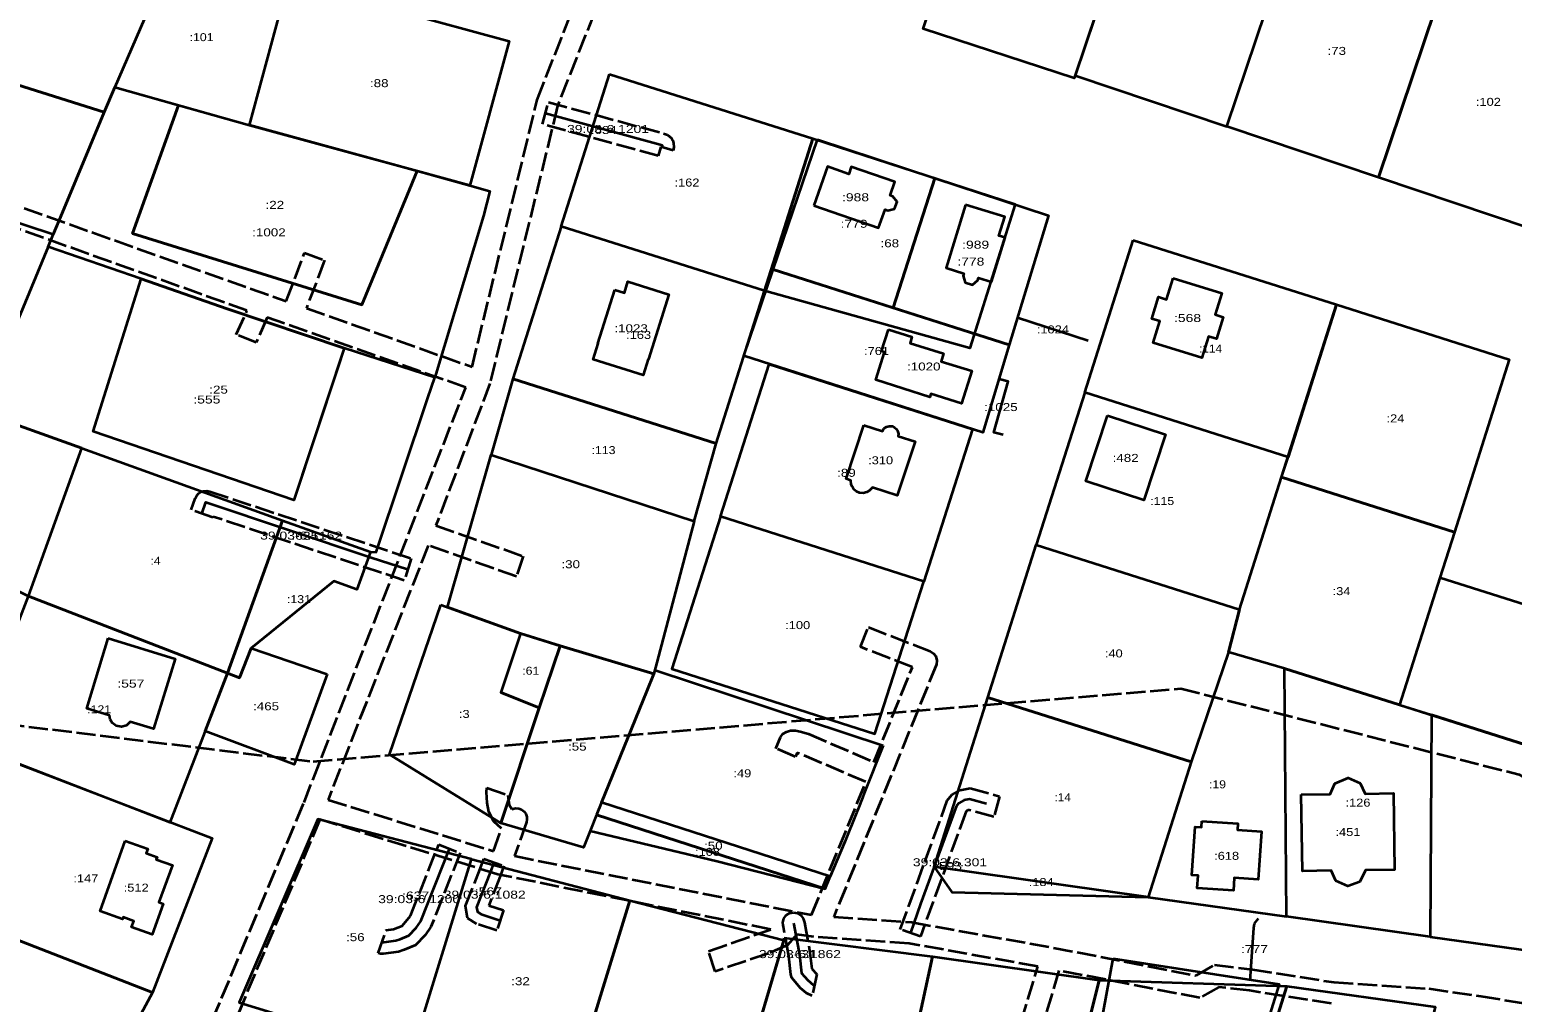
# Model space of a CAD drawing. Extents: x 1185507 to 1197690, y 352608 to 375774.
# Drawn here: x 1190399.7 to 1190677.6, y 364414.2 to 364596.7 of the extents above; entities that cross this region are included whole.
import ezdxf
from ezdxf.enums import TextEntityAlignment as Align

# ---------------------------------------------------------------- set-up
doc = ezdxf.new("R2010")
doc.units = 0
doc.header["$LTSCALE"] = 0.6
doc.linetypes.add('LONG_DASHED', pattern=[7.5, 6, -1.5])
for name, color, linetype, lineweight in [('2', 7, 'Continuous', 35), ('7', 7, 'LONG_DASHED', 35), ('8', 7, 'Continuous', 35)]:
    doc.layers.add(name, color=color, linetype=linetype, lineweight=lineweight)

msp = doc.modelspace()

# ---------------------------------------------------------------- linework, layer by layer
at = {"layer": '2'}
for points in [[(1190580.02, 364635.14), (1190608.39, 364625.95), (1190595.5, 364587.56), (1190567.19, 364596.87)], [(1190636.88, 364616.44), (1190608.44, 364626), (1190595.7, 364588.08), (1190624.14, 364578.52)], [(1190390.15, 364622), (1190419.82, 364614.11), (1190426.83, 364611.77), (1190415.6, 364585.92), (1190413.64, 364581.23), (1190379.72, 364591.89), (1190388.94, 364618.53)], [(1190636.88, 364616.44), (1190665.31, 364606.88), (1190652.56, 364568.96), (1190624.14, 364578.52)], [(1190448.18, 364605.82), (1190426.83, 364611.77), (1190415.6, 364585.92), (1190440.87, 364578.79)], [(1190448.18, 364605.82), (1190489.54, 364594.5), (1190482.19, 364567.48), (1190440.87, 364578.79)], [(1190665.31, 364606.88), (1190693.75, 364597.33), (1190681, 364559.41), (1190652.56, 364568.96)], [(1190379.72, 364591.89), (1190413.64, 364581.23), (1190405.75, 364562.26), (1190404.09, 364558.27), (1190393.92, 364561.55), (1190395.35, 364565.66), (1190397.61, 364572.21), (1190393.97, 364573.3), (1190390.13, 364574.45), (1190375.41, 364578.85), (1190375.82, 364580.49), (1190375.86, 364580.73)], [(1190508.38, 364588.35), (1190546.5, 364576.26), (1190537.43, 364547.66), (1190499.3, 364559.76)], [(1190415.6, 364585.92), (1190427.54, 364582.55), (1190418.97, 364558.44), (1190461.97, 364545.09), (1190470.43, 364565.64), (1190472.3, 364570.19), (1190482.19, 364567.48), (1190485.93, 364566.36), (1190484.73, 364561.73), (1190475.61, 364531.4), (1190458.61, 364536.92), (1190436.72, 364544.33), (1190420.58, 364549.92), (1190403.12, 364555.96), (1190404.09, 364558.27), (1190405.75, 364562.26), (1190413.65, 364581.23)], [(1190427.54, 364582.55), (1190440.87, 364578.79), (1190472.3, 364570.19), (1190470.43, 364565.64), (1190461.97, 364545.09), (1190418.97, 364558.44)], [(1190546.5, 364576.26), (1190584.43, 364563.93), (1190575.92, 364536.96), (1190537.43, 364547.66)], [(1190547.4, 364576.06), (1190569.38, 364568.83), (1190561.59, 364544.48), (1190539.09, 364551.67)], [(1190569.38, 364568.83), (1190590.66, 364561.84), (1190583.33, 364537.53), (1190561.59, 364544.48)], [(1190537.43, 364547.66), (1190499.3, 364559.76), (1190490.23, 364531.17), (1190528.35, 364519.07)], [(1190606.54, 364557.2), (1190644.66, 364545.1), (1190635.6, 364516.5), (1190597.47, 364528.6)], [(1190403.12, 364555.96), (1190397.62, 364542.61), (1190395.42, 364537.28), (1190390.17, 364525.06), (1190409.42, 364518.15), (1190447.07, 364504.63), (1190463.54, 364498.72), (1190464.61, 364498.63), (1190474.33, 364527.61), (1190475.61, 364531.4), (1190458.61, 364536.92), (1190457.36, 364533.13), (1190449.18, 364508.39), (1190411.55, 364521.27), (1190420.58, 364549.92)], [(1190539.09, 364551.67), (1190583.33, 364537.53), (1190578.4, 364521.14), (1190533.56, 364535.47)], [(1190420.58, 364549.92), (1190436.72, 364544.33), (1190458.61, 364536.92), (1190449.18, 364508.39), (1190411.55, 364521.27)], [(1190644.67, 364545.1), (1190677.08, 364534.82), (1190666.8, 364502.41), (1190634.39, 364512.7)], [(1190538.33, 364533.93), (1190576.42, 364521.74), (1190567.28, 364493.17), (1190529.18, 364505.36)], [(1190486.16, 364516.93), (1190524.23, 364504.45), (1190528.35, 364519.07), (1190490.23, 364531.17)], [(1190635.6, 364516.5), (1190597.47, 364528.6), (1190588.4, 364500.01), (1190626.52, 364487.91), (1190634.39, 364512.7)], [(1190409.42, 364518.15), (1190390.17, 364525.06), (1190382.4, 364507.25), (1190391.55, 364494.27), (1190399.45, 364490.39)], [(1190409.42, 364518.15), (1190447.07, 364504.63), (1190436.76, 364475.93), (1190399.45, 364490.39)], [(1190477.98, 364488.36), (1190486.16, 364516.93), (1190524.23, 364504.45), (1190516.66, 364475.86), (1190499.15, 364481.1), (1190491.7, 364483.43)], [(1190624.44, 364479.92), (1190626.52, 364487.91), (1190634.39, 364512.7), (1190666.8, 364502.41), (1190664.07, 364493.84), (1190656.51, 364470), (1190634.95, 364476.85)], [(1190463.54, 364498.72), (1190461, 364491.66), (1190456.68, 364493.22), (1190441.17, 364480.66), (1190439, 364475.06), (1190436.76, 364475.93), (1190447.07, 364504.63)], [(1190567.28, 364493.17), (1190529.18, 364505.36), (1190520.04, 364476.78), (1190558.13, 364464.59)], [(1190588.4, 364500.01), (1190626.52, 364487.91), (1190624.44, 364479.92), (1190617.45, 364459.32), (1190579.32, 364471.42)], [(1190682.39, 364492.06), (1190681.23, 364488.39), (1190664.07, 364493.84), (1190656.51, 364470), (1190698.44, 364456.69), (1190707.18, 364484.19)], [(1190436.76, 364475.93), (1190425.92, 364447.96), (1190388.63, 364462.41), (1190399.45, 364490.39)], [(1190476.78, 364488.79), (1190491.7, 364483.43), (1190487.98, 364472.31), (1190495.19, 364469.46), (1190488.02, 364447.83), (1190467.1, 364460.71)], [(1190488.09, 364472.34), (1190491.77, 364483.38), (1190499.15, 364481.1), (1190495.19, 364469.46)], [(1190455.42, 364475.8), (1190449.28, 364458.83), (1190432.55, 364465.07), (1190436.76, 364475.93), (1190439, 364475.06), (1190441.17, 364480.66)], [(1190495.19, 364469.46), (1190499.15, 364481.1), (1190516.66, 364475.86), (1190515.38, 364472.61), (1190506.88, 364451.68), (1190505.94, 364449.37), (1190504.73, 364446.38), (1190503.53, 364443.26), (1190488.02, 364447.83)], [(1190624.44, 364479.92), (1190617.45, 364459.32), (1190609.4, 364433.94), (1190635.32, 364430.28), (1190634.95, 364476.85)], [(1190559.69, 364462.39), (1190556.12, 364453.45), (1190555.8, 364452.6), (1190554.99, 364450.48), (1190554.71, 364449.73), (1190552.47, 364444.34), (1190551.1, 364441.07), (1190549.74, 364437.81), (1190506.88, 364451.68), (1190515.38, 364472.61), (1190516.66, 364475.86), (1190516.96, 364476.55)], [(1190634.95, 364476.85), (1190656.51, 364470), (1190662.46, 364468.12), (1190662.24, 364426.49), (1190635.32, 364430.28)], [(1190579.32, 364471.42), (1190617.45, 364459.32), (1190609.4, 364433.94), (1190569.23, 364439.6)], [(1190698.44, 364456.69), (1190662.46, 364468.12), (1190662.24, 364426.49), (1190687.72, 364422.9), (1190698.15, 364455.75)], [(1190397.68, 364458.91), (1190433.86, 364445.01), (1190422.7, 364416.02), (1190386.53, 364430.1)], [(1190506.88, 364451.68), (1190505.94, 364449.37), (1190548.79, 364435.51), (1190549.74, 364437.81)], [(1190505.94, 364449.37), (1190504.73, 364446.38), (1190528.54, 364440.71), (1190548.79, 364435.51)], [(1190482.5, 364441.06), (1190453.71, 364448.57), (1190438.94, 364414.18), (1190471.2, 364404.29)], [(1190482.5, 364441.06), (1190512.2, 364433.34), (1190500.51, 364395.28), (1190471.2, 364404.29)], [(1190609.4, 364433.94), (1190569.23, 364439.6), (1190572.53, 364434.9)], [(1190377.5, 364433.71), (1190386.53, 364430.1), (1190422.7, 364416.02), (1190412.2, 364396.54), (1190398.99, 364372.06), (1190382.22, 364376.24), (1190378.43, 364377.18), (1190370.06, 364414.67), (1190372.09, 364419.87)], [(1190512.2, 364433.34), (1190541.04, 364425.84), (1190529.71, 364387.33), (1190500.51, 364395.28)], [(1190541.14, 364426.28), (1190568.91, 364422.79), (1190560.72, 364385), (1190560.1, 364382.18), (1190529.71, 364387.33), (1190541.04, 364425.84)], [(1190568.91, 364422.79), (1190600.18, 364418.38), (1190590.77, 364380.48), (1190560.72, 364385)], [(1190602.8, 364422.44), (1190633.95, 364417.63), (1190620.97, 364375.98), (1190594.87, 364379.16)], [(1190600.18, 364418.38), (1190635.34, 364417.21), (1190624.43, 364382.3), (1190591.51, 364383.45)], [(1190635.34, 364417.21), (1190663.17, 364413.36), (1190662.28, 364409.63), (1190661.35, 364405.72), (1190654.11, 364375.27), (1190653.46, 364372.51), (1190623.38, 364379.05), (1190624.43, 364382.3), (1190633.8, 364412.26), (1190634.99, 364416.08)]]:
    msp.add_lwpolyline(points, close=True, dxfattribs=at)
at = {"layer": '7'}
for points in [[(1190390.14, 364566.2), (1190447.76, 364545.74), (1190451.22, 364554.84), (1190454.96, 364553.42), (1190451.55, 364544.45), (1190482.61, 364533.41), (1190494.81, 364583.53), (1190504.74, 364608.72), (1190490.08, 364620.47), (1190489.64, 364621.08), (1190489.45, 364621.8), (1190489.55, 364622.55), (1190489.92, 364623.22), (1190498.88, 364634.62), (1190518.92, 364673.75), (1190545.81, 364714.13), (1190550.54, 364722.34), (1190549.28, 364723.55), (1190536.3, 364747.95), (1190523.65, 364763.79), (1190521.95, 364765.46), (1190506.35, 364767.58), (1190505.27, 364771.78)], [(1190508.85, 364608.28), (1190498.64, 364582.41), (1190485.96, 364530.3), (1190475.82, 364503.67), (1190492.18, 364497.92), (1190490.92, 364494.12), (1190474.39, 364499.93), (1190455.6, 364452.22), (1190486.65, 364442.57), (1190488.14, 364446.84), (1190486.68, 364448.15), (1190485.77, 364449.92), (1190485.42, 364451.66), (1190485.29, 364453.65), (1190485.4, 364454.44), (1190489.34, 364453.1), (1190489.59, 364451.24), (1190490.08, 364450.47), (1190490.76, 364450.63), (1190491.39, 364450.58), (1190491.85, 364450.39), (1190492.35, 364450.01), (1190492.67, 364449.55), (1190492.86, 364449.02), (1190492.89, 364448.51), (1190492.79, 364448.02), (1190490.57, 364441.66), (1190546.25, 364430.6), (1190556.45, 364455.57), (1190543.57, 364461.04), (1190543.25, 364460.24), (1190539.59, 364461.85), (1190540.46, 364463.97), (1190540.9, 364464.58), (1190541.53, 364464.98), (1190542.34, 364465.2), (1190543.26, 364465.18), (1190544.11, 364465.01), (1190545.7, 364464.58), (1190557.95, 364459.28), (1190565.16, 364477.09), (1190555.44, 364480.89), (1190556.92, 364484.61), (1190568.51, 364480.07), (1190569.14, 364479.67), (1190569.53, 364479.15), (1190569.77, 364478.34), (1190569.67, 364477.59), (1190550.42, 364430.24), (1190565.04, 364429.22), (1190591.64, 364424.45), (1190618.37, 364419.24), (1190621.81, 364421.21), (1190628.91, 364420.37), (1190644.21, 364417.96), (1190661.99, 364416.78), (1190671.72, 364415.36), (1190683.02, 364413.49)], [(1189191.9, 364549.27), (1189395.22, 364588.56), (1189548.85, 364595.13), (1189680.04, 364579.91), (1189784.57, 364598.37), (1189872.95, 364591.01), (1190232.66, 364472.66), (1190283.77, 364463.98), (1190368.24, 364469.75), (1190452.8, 364459.37), (1190615.51, 364473.08), (1190678.91, 364456.96), (1190881.18, 364333.99), (1190940.56, 364356.34), (1190991.35, 364354.82), (1191177.32, 364502.05)], [(1190481.42, 364529.58), (1190444.22, 364542.68), (1190442.12, 364537.97), (1190438.41, 364539.48), (1190440.41, 364543.98), (1190388.71, 364562.46)], [(1190432.15, 364406.69), (1190451.1, 364451.71), (1190481.42, 364529.58)], [(1190585.51, 364410.41), (1190588.69, 364420.92), (1190564.54, 364425.24), (1190546.69, 364426.49), (1190543.52, 364426.96), (1190541.73, 364424.92), (1190538.19, 364423.38), (1190528.17, 364420.02), (1190526.95, 364423.83), (1190538.6, 364427.88), (1190487.42, 364438.21), (1190454.09, 364448.5), (1190435.81, 364405.08)], [(1190643.74, 364413.98), (1190628.38, 364416.4), (1190622.63, 364417.08), (1190619.08, 364415.02), (1190592.65, 364420.18), (1190589.41, 364409.53)]]:
    msp.add_lwpolyline(points, dxfattribs=at)
for points in [[(1190496.92, 364583.11), (1190518.52, 364577.22), (1190519.23, 364576.94), (1190519.64, 364576.67), (1190519.99, 364576.31), (1190520.24, 364575.87), (1190520.38, 364575.39), (1190520.41, 364574.64), (1190520.3, 364574.02), (1190518.03, 364574.7), (1190517.51, 364573.01), (1190495.79, 364578.96)], [(1190429.93, 364506.58), (1190430.69, 364508.74), (1190430.99, 364509.32), (1190431.34, 364509.68), (1190431.75, 364509.95), (1190432.22, 364510.12), (1190432.85, 364510.17), (1190433.47, 364510.05), (1190471.18, 364497.49), (1190469.88, 364493.37), (1190434.05, 364505.32), (1190434, 364505.17)], [(1190581.52, 364452.83), (1190580.43, 364448.98), (1190575.82, 364450.28), (1190575.56, 364450.23), (1190575.22, 364450.04), (1190566.68, 364426.57), (1190562.9, 364427.89), (1190571.7, 364452.05), (1190572.57, 364453.13), (1190574.14, 364454.03), (1190575.98, 364454.4)], [(1190466.48, 364427.72), (1190467.87, 364427.92), (1190469.52, 364428.56), (1190471.08, 364430.44), (1190476.36, 364443.82), (1190480.37, 364442.25), (1190474.9, 364428.38), (1190473.8, 364426.82), (1190472.02, 364424.96), (1190469.85, 364424.03), (1190468.81, 364423.7), (1190465.96, 364423.31), (1190465.46, 364423.31), (1190465, 364423.42)], [(1190484.8, 364441.14), (1190488.56, 364439.8), (1190487.87, 364437.86), (1190485.73, 364432.39), (1190488.49, 364431.48), (1190487.23, 364427.68), (1190483.42, 364428.94), (1190481.77, 364430.02), (1190481.4, 364432.29), (1190484.13, 364439.26)], [(1190547.27, 364419.49), (1190546.36, 364415.44), (1190545.33, 364415.93), (1190544.19, 364416.89), (1190542.58, 364418.8), (1190542.4, 364419.43), (1190542.02, 364422.85), (1190541, 364428.38), (1190540.92, 364428.7), (1190540.89, 364429.2), (1190541.08, 364429.93), (1190541.52, 364430.53), (1190542.15, 364430.93), (1190542.89, 364431.07), (1190543.62, 364430.93), (1190544.26, 364430.53), (1190544.7, 364429.93), (1190544.92, 364429.21), (1190545.96, 364423.52), (1190546.31, 364420.51)]]:
    msp.add_lwpolyline(points, close=True, dxfattribs=at)
at = {"layer": '8'}
msp.add_line((1190598.12, 364538.28), (1190584.89, 364542.62), dxfattribs=at)
for points in [[(1190496.36, 364581.03), (1190517.86, 364575.17), (1190518.26, 364575.02), (1190518.26, 364574.69)], [(1190582.2, 364520.67), (1190580.41, 364521.12), (1190583.11, 364530.66), (1190581.41, 364531.09)], [(1190431.97, 364505.88), (1190432.72, 364508.03), (1190463.68, 364497.63), (1190470.53, 364495.44)], [(1190579.05, 364451.45), (1190575.9, 364452.34), (1190574.85, 364452.13), (1190573.89, 364451.58), (1190573.46, 364451.05), (1190566.7, 364432.69), (1190564.79, 364427.23)], [(1190465.71, 364425.45), (1190468.34, 364425.81), (1190469.11, 364426.05), (1190470.77, 364426.76), (1190472.13, 364428.19), (1190472.99, 364429.41), (1190478.36, 364443.03)], [(1190486.68, 364440.47), (1190486, 364438.56), (1190483.46, 364432.07), (1190483.6, 364431.21), (1190484.29, 364430.76), (1190487.86, 364429.58)], [(1190628.58, 364418.46), (1190628.53, 364419.04), (1190628.59, 364420.06), (1190629.17, 364428.21), (1190629.3, 364429.01), (1190630.06, 364429.94)], [(1190542.89, 364429.07), (1190542.95, 364428.83), (1190544, 364423.14), (1190544.39, 364419.66), (1190544.94, 364419.05), (1190545.22, 364418.74), (1190545.26, 364418.69), (1190545.56, 364418.35), (1190546.62, 364417.45), (1190546.64, 364417.44)]]:
    msp.add_lwpolyline(points, dxfattribs=at)
for points in [[(1190546.7, 364563.71), (1190558.84, 364559.5), (1190560.04, 364562.94), (1190560.59, 364562.75), (1190561.84, 364563.07), (1190562.3, 364564.39), (1190561.51, 364565.39), (1190561, 364565.57), (1190561.88, 364568.11), (1190553.69, 364570.96), (1190553.22, 364569.6), (1190549.22, 364570.99)], [(1190575.15, 364563.85), (1190571.51, 364551.99), (1190574.82, 364550.97), (1190574.68, 364550.51), (1190575.06, 364549.26), (1190576.43, 364548.84), (1190577.43, 364549.66), (1190577.57, 364550.13), (1190580, 364549.38), (1190582.54, 364557.67), (1190581.38, 364558.03), (1190582.48, 364561.6)], [(1190509.4, 364547.87), (1190511.16, 364547.31), (1190511.84, 364549.46), (1190519.53, 364547.01), (1190515.71, 364534.85), (1190515.63, 364534.88), (1190514.67, 364531.87), (1190505.32, 364534.81), (1190506.26, 364537.8), (1190506.2, 364537.82)], [(1190614.08, 364550.08), (1190623.21, 364547.23), (1190621.96, 364543.23), (1190623.45, 364542.77), (1190622.2, 364538.66), (1190620.67, 364539.11), (1190619.42, 364535.1), (1190610.28, 364537.96), (1190611.54, 364541.98), (1190610.05, 364542.43), (1190611.31, 364546.56), (1190612.83, 364546.09)], [(1190560.69, 364540.44), (1190565.07, 364539.06), (1190564.72, 364537.9), (1190571, 364535.91), (1190570.54, 364534.46), (1190576.3, 364532.65), (1190574.37, 364526.55), (1190568.6, 364528.34), (1190568.42, 364527.77), (1190558.29, 364530.99), (1190559.93, 364536.18), (1190559.36, 364536.36)], [(1190601.75, 364524.3), (1190612.6, 364520.74), (1190608.55, 364508.39), (1190597.69, 364511.95)], [(1190556.05, 364522.5), (1190559.53, 364521.39), (1190559.82, 364521.83), (1190560.3, 364522.19), (1190560.84, 364522.33), (1190561.38, 364522.3), (1190561.84, 364522.08), (1190562.14, 364521.82), (1190562.4, 364521.4), (1190562.54, 364520.86), (1190562.51, 364520.45), (1190565.66, 364519.45), (1190562.32, 364509.3), (1190557.66, 364510.81), (1190557.13, 364510.22), (1190556.6, 364509.9), (1190555.96, 364509.75), (1190555.23, 364509.8), (1190554.66, 364510.05), (1190554.2, 364510.44), (1190553.86, 364510.96), (1190553.7, 364511.38), (1190553.65, 364512.11), (1190552.75, 364512.41)], [(1190414.38, 364482.51), (1190426.92, 364478.64), (1190422.89, 364465.49), (1190418.51, 364466.82), (1190417.8, 364466.15), (1190416.86, 364465.88), (1190415.9, 364466.05), (1190415.12, 364466.63), (1190414.75, 364467.27), (1190414.63, 364468.03), (1190410.35, 364469.35)], [(1190638.07, 364453.19), (1190643.5, 364453.25), (1190644.35, 364455.23), (1190646.85, 364456.31), (1190649.1, 364455.34), (1190650.03, 364453.32), (1190655.38, 364453.43), (1190655.58, 364439.07), (1190650.12, 364439.01), (1190649.05, 364436.84), (1190646.78, 364436.02), (1190644.56, 364437), (1190643.67, 364438.96), (1190638.3, 364438.83)], [(1190619.44, 364448.21), (1190626.2, 364447.75), (1190626.12, 364446.57), (1190630.61, 364446.27), (1190629.99, 364437.27), (1190625.5, 364437.57), (1190625.34, 364435.17), (1190618.57, 364435.63), (1190618.73, 364437.99), (1190617.55, 364438.07), (1190618.17, 364447.12), (1190619.36, 364447.04)], [(1190417.58, 364444.52), (1190421.81, 364442.98), (1190421.52, 364442.18), (1190423.55, 364441.45), (1190423.39, 364441), (1190426.42, 364439.91), (1190423.91, 364432.97), (1190424.69, 364432.69), (1190422.61, 364426.92), (1190418.75, 364428.31), (1190419.18, 364429.45), (1190417.21, 364430.18), (1190417.08, 364429.82), (1190412.85, 364431.34)]]:
    msp.add_lwpolyline(points, close=True, dxfattribs=at)

# ---------------------------------------------------------------- texts
at = {"layer": '2'}
for s, width, p in [(':101', 1.15, (1190431.8895, 364594.53)), (':73', 1.25, (1190644.7245, 364591.95)), (':88', 1.25, (1190465.2045, 364585.9)), (':102', 1.2, (1190673.155, 364582.395)), (':162', 1.2, (1190522.9, 364567.255)), (':22', 1.25, (1190445.6345, 364563.07)), (':779', 1.3, (1190554.2355, 364559.52)), (':1002', 1.25, (1190444.525, 364557.91)), (':68', 1.25, (1190560.9295, 364555.86)), (':778', 1.3, (1190576.1255, 364552.43)), (':163', 1.2, (1190513.83, 364538.665)), (':761', 1.2, (1190558.445, 364535.655)), (':114', 1.1, (1190621.065, 364536.1)), (':25', 1.25, (1190435.0795, 364528.405)), (':555', 1.3, (1190432.8905, 364526.545)), (':24', 1.2, (1190655.7345, 364523.005)), (':113', 1.15, (1190507.2545, 364517.06)), (':89', 1.25, (1190552.7995, 364512.8)), (':115', 1.15, (1190611.9995, 364507.505)), (':4', 1.15, (1190423.26, 364496.29)), (':30', 1.25, (1190501.1045, 364495.645)), (':131', 1.15, (1190450.1495, 364489.095)), (':34', 1.2, (1190645.6195, 364490.6)), (':100', 1.2, (1190543.66, 364484.225)), (':40', 1.2, (1190602.9195, 364478.915)), (':61', 1.15, (1190493.62, 364475.67)), (':121', 1.15, (1190412.6945, 364468.425)), (':465', 1.25, (1190443.9855, 364468.995)), (':3', 1.2, (1190481.1455, 364467.56)), (':55', 1.25, (1190502.3395, 364461.43)), (':49', 1.2, (1190533.2845, 364456.43)), (':19', 1.15, (1190622.36, 364454.35)), (':14', 1.1, (1190593.3405, 364451.93)), (':126', 1.2, (1190648.705, 364450.92)), (':108', 1.2, (1190526.76, 364441.69)), (':50', 1.25, (1190527.8395, 364442.845)), (':147', 1.2, (1190410.195, 364436.715)), (':184', 1.2, (1190589.315, 364436.02)), (':56', 1.25, (1190460.7195, 364425.68)), (':32', 1.25, (1190491.6995, 364417.42))]:
    msp.add_text(s, height=1.5, dxfattribs=dict(at, width=width)).set_placement(p, align=Align.CENTER)
at = {"layer": '7', "width": 1.3}
for s, p in [('39:03-6.1201', (1190508.1, 364577.31)), ('39:03-6.1162', (1190450.555, 364501.02)), ('39:03-6.301', (1190572.2095, 364439.735)), ('39:03-6.1082', (1190484.9805, 364433.66)), ('39:03-6.1200', (1190472.6855, 364432.815)), ('39:03-6.1862', (1190544.0805, 364422.505))]:
    msp.add_text(s, height=1.5, dxfattribs=at).set_placement(p, align=Align.CENTER)
at = {"layer": '8'}
for s, width, p in [(':634', 1.25, (1190507.3105, 364577.11)), (':988', 1.3, (1190554.5005, 364564.495)), (':989', 1.3, (1190577.0255, 364555.595)), (':568', 1.3, (1190616.7505, 364541.84)), (':1023', 1.25, (1190512.425, 364539.915)), (':1024', 1.2, (1190591.505, 364539.7)), (':1020', 1.25, (1190567.295, 364532.745)), (':1025', 1.25, (1190581.76, 364525.13)), (':310', 1.2, (1190559.205, 364515.15)), (':482', 1.25, (1190605.1455, 364515.595)), (':635', 1.3, (1190451.2505, 364500.985)), (':557', 1.3, (1190418.6355, 364473.25)), (':451', 1.2, (1190646.825, 364445.415)), (':593', 1.3, (1190571.9205, 364439.035)), (':618', 1.2, (1190624.08, 364440.94)), (':512', 1.2, (1190419.635, 364434.97)), (':637', 1.3, (1190472.0355, 364433.49)), (':567', 1.3, (1190485.6605, 364434.275)), (':631', 1.2, (1190544.765, 364422.505)), (':777', 1.3, (1190629.2955, 364423.45))]:
    msp.add_text(s, height=1.5, dxfattribs=dict(at, width=width)).set_placement(p, align=Align.CENTER)

doc.saveas('drawing.dxf')
